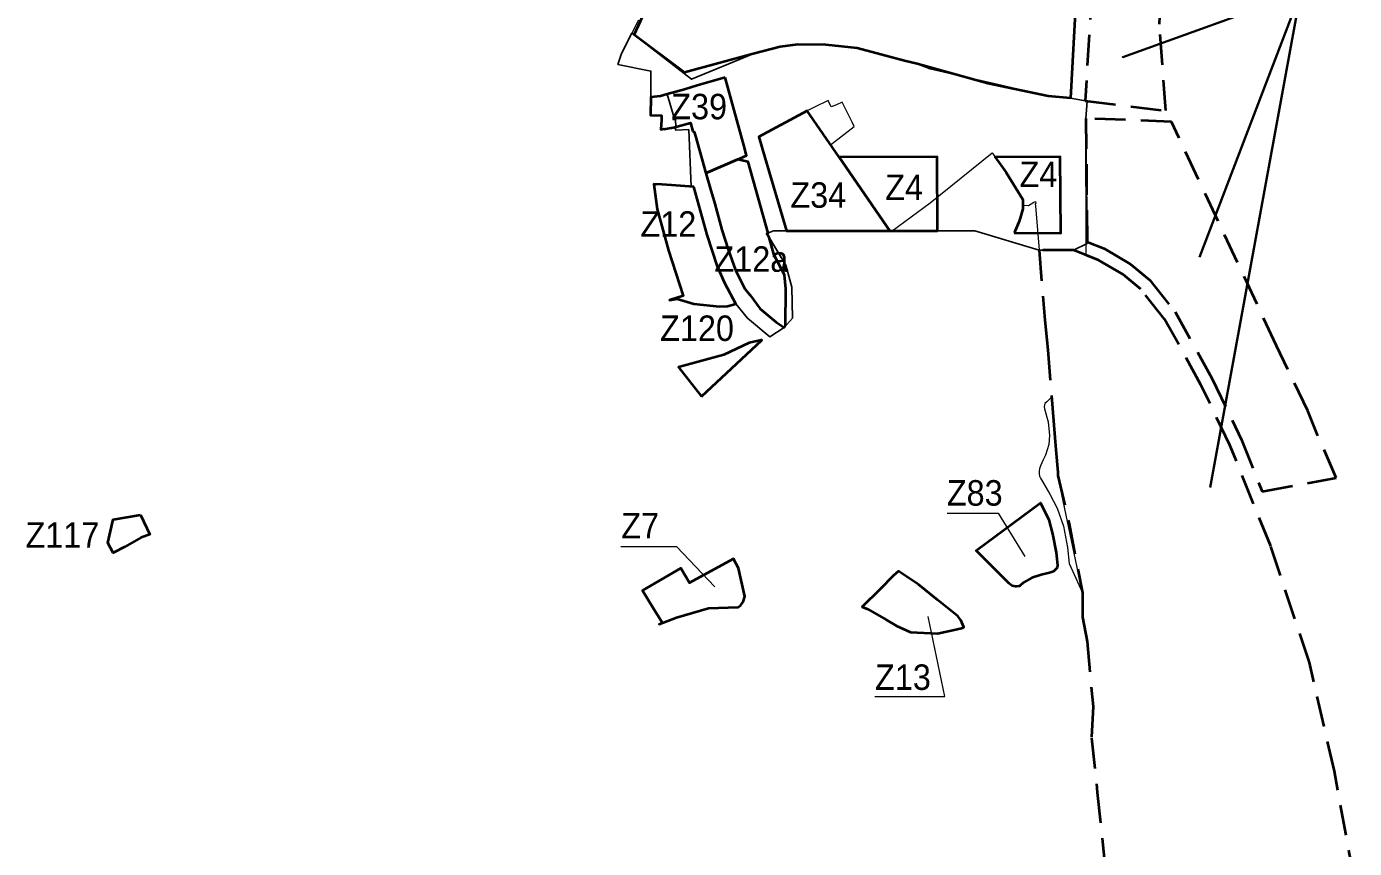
# Model space of a CAD drawing. Extents: x -650276 to -642489, y -1074311 to -1066658.
# Drawn here: x -646452 to -645202, y -1070697 to -1069923 of the extents above; entities that cross this region are included whole.
import ezdxf

# ---------------------------------------------------------------- set-up
doc = ezdxf.new("R2010")
doc.units = 0
doc.header["$LTSCALE"] = 9.6
doc.linetypes.add('MEDIUM_DASHED', pattern=[4.5, 3, -1.5])
for name, color, linetype, lineweight in [('42', 7, 'Continuous', 25), ('44', 7, 'Continuous', 40), ('45', 7, 'Continuous', 40), ('46', 7, 'Continuous', 13), ('61', 7, 'MEDIUM_DASHED', 40), ('62', 7, 'Continuous', 35), ('63', 7, 'Continuous', 13)]:
    doc.layers.add(name, color=color, linetype=linetype, lineweight=lineweight)

msp = doc.modelspace()

# ---------------------------------------------------------------- linework, layer by layer
at = {"layer": '42'}
msp.add_lwpolyline([(-645637.56, -1070114.89), (-645559.63, -1070114.85), (-645499.129, -1070133.293), (-645466.862, -1070133.219), (-645454.051, -1070127.008), (-645455.073, -1070009.111), (-645453.852, -1069992.968), (-645469.701, -1069990.011), (-645490.814, -1069988.074), (-645601.753, -1069962.317), (-645614.072, -1069957.797), (-645625.979, -1069954.92), (-645670.325, -1069943.002), (-645699.889, -1069939.714), (-645726.542, -1069939.398), (-645742.967, -1069941.862), (-645768.424, -1069948.431), (-645826.321, -1069972.247), (-645880.431, -1069930.3), (-645882.381, -1069928.788), (-645892.09, -1069947.98), (-645895.66, -1069958.42), (-645864.48, -1069964.53), (-645864.77, -1069989.26), (-645855.54, -1069988.24), (-645849.1, -1069986.42), (-645842.8, -1070008.59), (-645843.74, -1070010.25), (-645841.43, -1070010.21), (-645841.21, -1070017.31), (-645841.89, -1070017.42), (-645841.075, -1070020.163), (-645828.963, -1070019.709), (-645826.615, -1070073.495), (-645824.28, -1070073.67), (-645811.48, -1070118.65), (-645801.99, -1070148.51), (-645795.07, -1070164.26), (-645784.51, -1070183.77), (-645773.48, -1070197.1), (-645752.54, -1070214.74), (-645739.12, -1070205.9), (-645731.3, -1070197.24), (-645731.94, -1070167.87), (-645737.63, -1070147.39), (-645755.4, -1070117.6), (-645749.28, -1070114.96), (-645737.075, -1070114.955)], close=True, dxfattribs=at)
at = {"layer": '44', "lineweight": 13}
msp.add_lwpolyline([(-645585.63, -1070380.811), (-645537.799, -1070380.811), (-645512.608, -1070421.471)], dxfattribs=at)
msp.add_lwpolyline([(-645585.63, -1070380.811), (-645537.799, -1070380.811), (-645512.608, -1070421.471)], dxfattribs=at)
at = {"layer": '44'}
msp.add_lwpolyline([(-645497.81, -1070370.93), (-645497.81, -1070370.93), (-645490.19, -1070386.97), (-645486.54, -1070400.38), (-645483.29, -1070417.99), (-645482.62, -1070423.93), (-645481.93, -1070430.04), (-645482.18, -1070432.13), (-645485.67, -1070435.7), (-645489.34, -1070437.05), (-645497.33, -1070438.82), (-645505.88, -1070441.74), (-645513.81, -1070446.24), (-645517.44, -1070449.23), (-645517.95, -1070449.45), (-645520.4, -1070449.87), (-645521.41, -1070449.84), (-645522.95, -1070449.61), (-645524.42, -1070449.16), (-645525.75, -1070448.41), (-645527.34, -1070447.1), (-645558.36, -1070416.1)], close=True, dxfattribs=at)
at = {"layer": '45'}
msp.add_line((-645726.542, -1069939.398), (-645742.967, -1069941.862), dxfattribs=at)
for points in [[(-645500.137, -1069632.833), (-645498, -1069648), (-645495, -1069688), (-645495, -1069744), (-645495, -1069766), (-645504.976, -1069763.332), (-645527, -1069858), (-645459.312, -1069864.01), (-645464.288, -1069895.362), (-645465.756, -1069921.035), (-645469.701, -1069990.011)], [(-645742.967, -1069941.862), (-645768.424, -1069948.431), (-645833, -1069966), (-645880.431, -1069930.3), (-645874.219, -1069917.496), (-645869.262, -1069905.935), (-645863.95, -1069889.468), (-645857.289, -1069863.338), (-645857.204, -1069862.954), (-645850.92, -1069863.41), (-645849.79, -1069868.4), (-645808.84, -1069870.75), (-645808.28, -1069865.39), (-645804.185, -1069825.84)], [(-645469.701, -1069990.011), (-645490.814, -1069988.074), (-645547.4, -1069976.382), (-645614.072, -1069957.797), (-645625.979, -1069954.92), (-645670.325, -1069943.002), (-645699.889, -1069939.714), (-645726.542, -1069939.398)], [(-645794.679, -1069970.596), (-645821, -1069978), (-645833, -1069982)], [(-645794.679, -1069970.596), (-645821, -1069978), (-645833, -1069982)], [(-645777.143, -1070034.287), (-645786.238, -1070001.251), (-645794.679, -1069970.596)], [(-645777.143, -1070034.287), (-645786.238, -1070001.251), (-645794.679, -1069970.596)], [(-645833, -1069982), (-645849.1, -1069986.42), (-645855.54, -1069988.24), (-645864.77, -1069989.26), (-645864.97, -1070006.16), (-645854.42, -1070006.47), (-645854.65, -1070010.44), (-645855.17, -1070019.44), (-645852.36, -1070019.01), (-645852.33, -1070019.2), (-645845.37, -1070018.12), (-645845.14, -1070018.08), (-645845.17, -1070017.91), (-645841.89, -1070017.42), (-645827.365, -1070013.291), (-645825.08, -1070021.52)], [(-645833, -1069982), (-645849.1, -1069986.42), (-645855.54, -1069988.24), (-645864.77, -1069989.26), (-645864.97, -1070006.16), (-645854.42, -1070006.47), (-645854.65, -1070010.44), (-645855.17, -1070019.44), (-645852.36, -1070019.01), (-645852.33, -1070019.2), (-645845.37, -1070018.12), (-645845.14, -1070018.08), (-645845.17, -1070017.91), (-645841.89, -1070017.42), (-645827.365, -1070013.291), (-645825.08, -1070021.52)], [(-645825.08, -1070021.52), (-645823.76, -1070021.67), (-645822.549, -1070025.948), (-645812.76, -1070060.53), (-645783.063, -1070047.855), (-645774.423, -1070044.167), (-645777.143, -1070034.287)], [(-645825.08, -1070021.52), (-645823.76, -1070021.67), (-645822.549, -1070025.948), (-645812.76, -1070060.53), (-645783.063, -1070047.855), (-645774.423, -1070044.167), (-645777.143, -1070034.287)], [(-645753.182, -1070121.317), (-645755.4, -1070117.6), (-645754.333, -1070117.14), (-645772.853, -1070049.868), (-645783.063, -1070047.855), (-645812.76, -1070060.53), (-645808.721, -1070074.795), (-645804.52, -1070089.63), (-645797.66, -1070113.88), (-645791.72, -1070132.59)], [(-645824.28, -1070073.67), (-645845.01, -1070072.12), (-645854.25, -1070071.4), (-645861.74, -1070070.95), (-645858.53, -1070094.64), (-645847.88, -1070133.4)], [(-645795.07, -1070164.26), (-645801.99, -1070148.51), (-645811.48, -1070118.65), (-645824.28, -1070073.67)], [(-645737.756, -1070204.389), (-645737.624, -1070169.544), (-645738.79, -1070156.281), (-645748.62, -1070137.889), (-645753.182, -1070121.317)], [(-645847.88, -1070133.4), (-645834.31, -1070176.15), (-645847.2, -1070180.14), (-645839.82, -1070178.94), (-645824.12, -1070183.63), (-645799.91, -1070186.32), (-645792.37, -1070186.01), (-645784.51, -1070183.77), (-645795.07, -1070164.26)], [(-645791.72, -1070132.59), (-645784.83, -1070151.9), (-645776.26, -1070169.44), (-645771.246, -1070175.64)], [(-645771.246, -1070175.64), (-645761.78, -1070188.29), (-645746.73, -1070201.04), (-645739.12, -1070205.9), (-645737.756, -1070204.389)]]:
    msp.add_lwpolyline(points, dxfattribs=at)
for points in [[(-645639.638, -1070114.895), (-645687.31, -1070045.724), (-645717.36, -1070002.12), (-645762.868, -1070026.606), (-645757.215, -1070045.97), (-645737.075, -1070114.955)], [(-645639.638, -1070114.895), (-645687.31, -1070045.724), (-645717.36, -1070002.12), (-645762.868, -1070026.606), (-645757.215, -1070045.97), (-645737.075, -1070114.955)], [(-645639.638, -1070114.895), (-645594.733, -1070114.868), (-645595.2, -1070045.403), (-645687.31, -1070045.724)], [(-645639.638, -1070114.895), (-645594.733, -1070114.868), (-645595.2, -1070045.403), (-645687.31, -1070045.724)], [(-645522.587, -1070116.952), (-645478.664, -1070117.114), (-645479.429, -1070045.409), (-645540.433, -1070045.752), (-645530.3, -1070060.08), (-645514.49, -1070085.4), (-645514.56, -1070090.91), (-645514.61, -1070094.35), (-645517.02, -1070103.08), (-645518.35, -1070106.87), (-645521.73, -1070114.83)], [(-645522.587, -1070116.952), (-645478.664, -1070117.114), (-645479.429, -1070045.409), (-645540.433, -1070045.752), (-645530.3, -1070060.08), (-645514.49, -1070085.4), (-645514.56, -1070090.91), (-645514.61, -1070094.35), (-645517.02, -1070103.08), (-645518.35, -1070106.87), (-645521.73, -1070114.83)], [(-645816.9, -1070270.96), (-645760.05, -1070217.79), (-645760.91, -1070217.98), (-645772.08, -1070220.39), (-645795.85, -1070231.81), (-645833.92, -1070241.96), (-645838.53, -1070243.19)], [(-646344.93, -1070382.33), (-646336.25, -1070400.875), (-646344.26, -1070403.84), (-646359.769, -1070412.361), (-646370.56, -1070418.29), (-646375.63, -1070408.76), (-646370.624, -1070386.792)], [(-645862.66, -1070469.5), (-645853.98, -1070483.81), (-645856.87, -1070485.24), (-645840.59, -1070479), (-645810.44, -1070470.17), (-645782.57, -1070469.22), (-645780.38, -1070467.64), (-645777.8, -1070464.4), (-645776.04, -1070459.38), (-645782.13, -1070432.59), (-645786.9, -1070423.81), (-645804.58, -1070433.53), (-645828.24, -1070446.54), (-645836.32, -1070432.55), (-645872.35, -1070453.55)], [(-645862.66, -1070469.5), (-645853.98, -1070483.81), (-645856.87, -1070485.24), (-645840.59, -1070479), (-645810.44, -1070470.17), (-645782.57, -1070469.22), (-645780.38, -1070467.64), (-645777.8, -1070464.4), (-645776.04, -1070459.38), (-645782.13, -1070432.59), (-645786.9, -1070423.81), (-645804.58, -1070433.53), (-645828.24, -1070446.54), (-645836.32, -1070432.55), (-645872.35, -1070453.55)], [(-645594.769, -1070494.065), (-645577.47, -1070490.3), (-645571.13, -1070488.89), (-645569.97, -1070488.3), (-645572.86, -1070481.41), (-645575.7, -1070477.77), (-645591.49, -1070465.19), (-645594.62, -1070462.7), (-645612.77, -1070447.82), (-645631.63, -1070435.3), (-645636.42, -1070439.93), (-645648.9, -1070452.38), (-645665.6, -1070469.04), (-645660.29, -1070471.12), (-645643.4, -1070481.02), (-645633.35, -1070486.91), (-645620.22, -1070493)], [(-645594.769, -1070494.065), (-645577.47, -1070490.3), (-645571.13, -1070488.89), (-645569.97, -1070488.3), (-645572.86, -1070481.41), (-645575.7, -1070477.77), (-645591.49, -1070465.19), (-645594.62, -1070462.7), (-645612.77, -1070447.82), (-645631.63, -1070435.3), (-645636.42, -1070439.93), (-645648.9, -1070452.38), (-645665.6, -1070469.04), (-645660.29, -1070471.12), (-645643.4, -1070481.02), (-645633.35, -1070486.91), (-645620.22, -1070493)]]:
    msp.add_lwpolyline(points, close=True, dxfattribs=at)
at = {"layer": '46'}
for points in [[(-645892.796, -1070412.223), (-645840.481, -1070412.223), (-645804.515, -1070450.215)], [(-645892.796, -1070412.223), (-645840.481, -1070412.223), (-645804.515, -1070450.215)], [(-645653.64, -1070553.576), (-645587.872, -1070553.576), (-645603.567, -1070478.038)], [(-645653.64, -1070553.576), (-645587.872, -1070553.576), (-645603.567, -1070478.038)]]:
    msp.add_lwpolyline(points, dxfattribs=at)
at = {"layer": '61'}
for points in [[(-645374.642, -1069640.059), (-645376.605, -1069623.944), (-645435.877, -1069633.555), (-645431.642, -1069692.811), (-645434.826, -1069759.235), (-645443.679, -1069846.142), (-645449.445, -1069887.328), (-645455.84, -1069992.731), (-645379.881, -1070001.766), (-645385.95, -1069920.347), (-645382.14, -1069845.883), (-645378.587, -1069802.788), (-645374.542, -1069758.923), (-645371.563, -1069692.39)], [(-645374.685, -1070012.289), (-645455.073, -1070009.111), (-645454.066, -1070125.249), (-645437.885, -1070131.669), (-645413.129, -1070146.351), (-645394.98, -1070161.51), (-645371.209, -1070191.309), (-645336.176, -1070254.367), (-645308.702, -1070311.792), (-645289.153, -1070360.302), (-645219.594, -1070347.682), (-645238.856, -1070303.185), (-645246.433, -1070284.382), (-645275.729, -1070223.153)]]:
    msp.add_lwpolyline(points, close=True, dxfattribs=at)
msp.add_lwpolyline([(-645202.41, -1070726.571), (-645221.272, -1070623.729), (-645244.808, -1070521.357), (-645281.252, -1070412.013), (-645319.69, -1070316.63), (-645346.844, -1070259.875), (-645381.213, -1070198.011), (-645403.604, -1070169.942), (-645420.081, -1070156.179), (-645443.191, -1070142.473), (-645454.881, -1070137.836), (-645466.862, -1070133.22), (-645499.142, -1070133.293), (-645493.76, -1070199.15), (-645490.95, -1070226.89), (-645485.21, -1070298.03), (-645483.34, -1070321.17), (-645481.65, -1070342.07), (-645481.67, -1070345.39), (-645471, -1070391), (-645458.32, -1070455.91), (-645458.46, -1070478.86), (-645454.02, -1070501.52), (-645448.36, -1070563), (-645449.82, -1070592.72), (-645444.47, -1070643.85), (-645435.711, -1070727.497)], dxfattribs=at)
at = {"layer": '62'}
msp.add_line((-645253.165, -1069890.903), (-645338.143, -1070356.741), dxfattribs=at)
msp.add_lwpolyline([(-645205.454, -1069890.903), (-645253.165, -1069890.903), (-645480.406, -1069576.285), (-645253.165, -1069890.903), (-645466.774, -1069697.69), (-645253.165, -1069890.903), (-645479.043, -1069805.455), (-645253.165, -1069890.903), (-645420.426, -1069951.415), (-645253.165, -1069890.903), (-645348.178, -1070139.662)], dxfattribs=at)
at = {"layer": '63'}
for points in [[(-645876.15, -1069916.47), (-645892.09, -1069947.98), (-645895.66, -1069958.42), (-645894.25, -1069958.7), (-645864.48, -1069964.53), (-645864.77, -1069989.26), (-645855.54, -1069988.24), (-645849.1, -1069986.42), (-645842.8, -1070008.59), (-645843.74, -1070010.25), (-645842.34, -1070010.22), (-645841.43, -1070010.21), (-645841.32, -1070013.79), (-645841.21, -1070017.31), (-645841.89, -1070017.42), (-645841.075, -1070020.163), (-645828.963, -1070019.709), (-645826.615, -1070073.495), (-645824.28, -1070073.67), (-645811.48, -1070118.65), (-645801.99, -1070148.51), (-645795.07, -1070164.26), (-645784.51, -1070183.77), (-645773.48, -1070197.1), (-645752.54, -1070214.74), (-645739.12, -1070205.9), (-645731.3, -1070197.24), (-645731.94, -1070167.87), (-645737.63, -1070147.39), (-645744.75, -1070135.39), (-645755.4, -1070117.6), (-645749.28, -1070114.96), (-645744.39, -1070114.96), (-645683.72, -1070114.92), (-645637.56, -1070114.89), (-645601.8, -1070088.57), (-645543.32, -1070041.67), (-645530.3, -1070060.08), (-645514.49, -1070085.4), (-645514.56, -1070090.91), (-645509.06, -1070090.97), (-645504.06, -1070087.92), (-645502.45, -1070087.23), (-645502.17, -1070089.16), (-645503.04, -1070089.54), (-645502.55, -1070091.83), (-645499.84, -1070125.33), (-645499.129, -1070133.293)], [(-645454.881, -1070137.836), (-645455.073, -1070009.111), (-645453.852, -1069992.968), (-645469.701, -1069990.011), (-645465.756, -1069921.035)], [(-645499.129, -1070133.293), (-645466.862, -1070133.219), (-645454.881, -1070137.836)], [(-645487.361, -1070271.37), (-645487.361, -1070271.37), (-645491.94, -1070275.85), (-645493.8, -1070277.67), (-645494.57, -1070280.34), (-645494.12, -1070282.52), (-645490.79, -1070294.93), (-645489.31, -1070307.77), (-645490.03, -1070316.27), (-645493.05, -1070326.11), (-645495.44, -1070330.67), (-645497.83, -1070336.16), (-645498.75, -1070338.98), (-645499.01, -1070340.96), (-645499.09, -1070343.91)], [(-645481.67, -1070345.39), (-645483.34, -1070321.17), (-645484.27, -1070309.7), (-645485.21, -1070298.03), (-645487.361, -1070271.37)], [(-645499.09, -1070343.91), (-645499.09, -1070343.91), (-645498.74, -1070345.87), (-645498, -1070347.74), (-645496.02, -1070351.15), (-645488.99, -1070362.96), (-645482.16, -1070375.96), (-645476.12, -1070393.13), (-645472.61, -1070413.13), (-645470.99, -1070428.07)], [(-645470.99, -1070428.07), (-645470.99, -1070428.07), (-645458.32, -1070455.91), (-645481.67, -1070345.39)]]:
    msp.add_lwpolyline(points, dxfattribs=at)
msp.add_lwpolyline([(-645706.41, -1070018.01), (-645695.39, -1070034), (-645673.1, -1070016.78), (-645675.24, -1070012.51), (-645677.02, -1070008.93), (-645677.65, -1070007.66), (-645684.59, -1069993.87), (-645689.84, -1069996.37), (-645694.8, -1069998.22), (-645697.59, -1069992.31), (-645710.43, -1069998.39), (-645717.36, -1070002.12)], close=True, dxfattribs=at)

# ---------------------------------------------------------------- texts
at = {"layer": '44', "width": 0.95}
msp.add_text('Z83', height=24, dxfattribs=at).set_placement((-645586.057, -1070373.732))
msp.add_text('Z83', height=24, dxfattribs=at).set_placement((-645586.057, -1070373.732))
at = {"layer": '46', "width": 0.95}
for s, p in [('Z39', (-645845.387, -1070009.975)), ('Z39', (-645845.387, -1070009.975)), ('Z4', (-645517.623, -1070073.78)), ('Z4', (-645517.623, -1070073.78)), ('Z4', (-645644.02, -1070085.964)), ('Z4', (-645644.02, -1070085.964)), ('Z34', (-645733.26, -1070093.266)), ('Z34', (-645733.26, -1070093.266)), ('Z12', (-645874.409, -1070120.563)), ('Z12a', (-645804.738, -1070153.542)), ('Z120', (-645855.898, -1070218.668)), ('Z7', (-645892.427, -1070404.622)), ('Z7', (-645892.427, -1070404.622)), ('Z117', (-646453.122, -1070413.348)), ('Z13', (-645653.625, -1070547.221)), ('Z13', (-645653.625, -1070547.221))]:
    msp.add_text(s, height=24, dxfattribs=at).set_placement(p)

doc.saveas('drawing.dxf')
